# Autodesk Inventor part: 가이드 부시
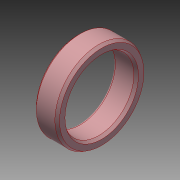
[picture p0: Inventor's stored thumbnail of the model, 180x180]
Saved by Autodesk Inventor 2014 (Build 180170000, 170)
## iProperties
Created: 2023-09
Part Number: 가이드 부시
Material: 스테인리스강
Document SubType Name: Modeling
Designer: mdu-01
Density: 1 g/cm^3
Appearance: 기본값(1)
Author: mdu-01
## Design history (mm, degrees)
sketch "스케치1"
  geometry: L1 (0, 0)-(12, 0); L2 (1, 18)-(10.5, 18); L3 (12, 18.866)-(12, 21.634); L4 (10.5, 22.5)-(1, 22.5); L5 (0, 21.5)-(0, 19); L6 (1, 22.5)-(0, 21.5); L7 (10.5, 22.5)-(12, 21.634); L8 (10.5, 18)-(12, 18.866); A1 r 1 centre (1, 19) between (0, 19) and (1, 18); 3 further points
  constraints: 16 end point, 8 point on line, 2 horizontal, 2 parallel, 2 point on circle, 2 tangent, 1 centre point, 1 perpendicular
  dimensions: "d0" = 12 distance of L1.start L1.end; "d1" = 36 diameter of L2 L1; "d2" = 45 diameter of L4 L1; "d3" = 1 radius of A1; "d4" = 1 distance of L4.end point (0, 22.5); "d5" = 1 distance of L5.start point (0, 22.5) (= d4); "d6" = 1.5 distance of L4.start point (12, 22.5); "d7" = 30 deg angle of L4 L7; "d8" = 1.5 distance of L2.end point (12, 18) (= d6); "d9" = 30 deg angle of L2 L8 (= d7)
revolve "회전1" sketch "스케치1" stored, may be unused: angle "d10" = 90 deg
node "솔리드1"
